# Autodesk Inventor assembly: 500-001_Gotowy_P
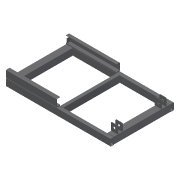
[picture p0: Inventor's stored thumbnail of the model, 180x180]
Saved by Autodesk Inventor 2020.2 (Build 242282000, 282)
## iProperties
Created: 2016-09
Part Number: 500-001_Gotowy_P
Document SubType Name: Assembly
Designer: F.Stasiak
Description: Podstawa
Manager: www.cadconsulting.pl
Company: Fabian Stasiak CAD Consulting
Author: F.Stasiak
Subject: Zbiór ćwiczeń. Autodesk Inventor 2020. Kurs podstawowy
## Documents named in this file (11)
- C:\2020_Kurs_podstawowy\R6 Zespoły\Warsztat\Komponenty\500-001_Gotowy_P.iam
- C:\2020_Kurs_podstawowy\R6 Zespoły\Warsztat\Komponenty\500-01-06.ipt
- C:\2020_Kurs_podstawowy\R6 Zespoły\Warsztat\Komponenty\500-01-07.ipt
- C:\2020_Kurs_podstawowy\R6 Zespoły\Warsztat\Komponenty\EN 10058 - 500-01-08.ipt
- C:\2020_Kurs_podstawowy\R6 Zespoły\Warsztat\Komponenty\DIN 120x60x4 500-01-01.ipt
- DIN 120x60x4 900-01-1.ipt
- C:\2020_Kurs_podstawowy\R6 Zespoły\Warsztat\Komponenty\DIN 120x60x4 500-01-02.ipt
- DIN 120x60x4 900-01-02.ipt
- C:\2020_Kurs_podstawowy\R6 Zespoły\Warsztat\Komponenty\DIN 120x60x4 500-01-04.ipt
- DIN 120x60x4 900-01-04.ipt
- C:\2020_Kurs_podstawowy\R6 Zespoły\Warsztat\Komponenty\500-01-08.ipt
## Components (15 placed, 7 different names)
1. 500-01-06:1 — Sztywne:13
2. 500-01-06:2 — Sztywne:12
3. 500-01-07:1 — Sztywne:14, Sztywne:9
4. 500-01-07:2 — Sztywne:14
5. 500-01-07:3 — Sztywne:7, Sztywne:8
6. 500-01-07:4 — Sztywne:7
7. EN 10058 - 500-01-08:1
8. EN 10058 - 500-01-08:2
9. DIN 120x60x4 500-01-01:1
10. DIN 120x60x4 500-01-02:1
11. DIN 120x60x4 500-01-04:1
12. DIN 120x60x4 500-01-01:2
13. DIN 120x60x4 500-01-04:2 — Sztywne:8, Sztywne:9
14. 500-01-08:1 — Sztywne:12
15. 500-01-08:2 — Sztywne:13
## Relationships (6: WeldJoint 6)
- Sztywne:7 [WeldJoint]: 500-01-07:3 ↔ 500-01-07:4
- Sztywne:8 [WeldJoint]: 500-01-07:3 ↔ DIN 120x60x4 500-01-04:2
- Sztywne:14 [WeldJoint]: 500-01-07:1 ↔ 500-01-07:2
- Sztywne:9 [WeldJoint]: 500-01-07:1 ↔ DIN 120x60x4 500-01-04:2
- Sztywne:12 [WeldJoint]: 500-01-06:2 ↔ 500-01-08:1
- Sztywne:13 [WeldJoint]: 500-01-06:1 ↔ 500-01-08:2
## Named parameters: d5_d13 = -143 mm
